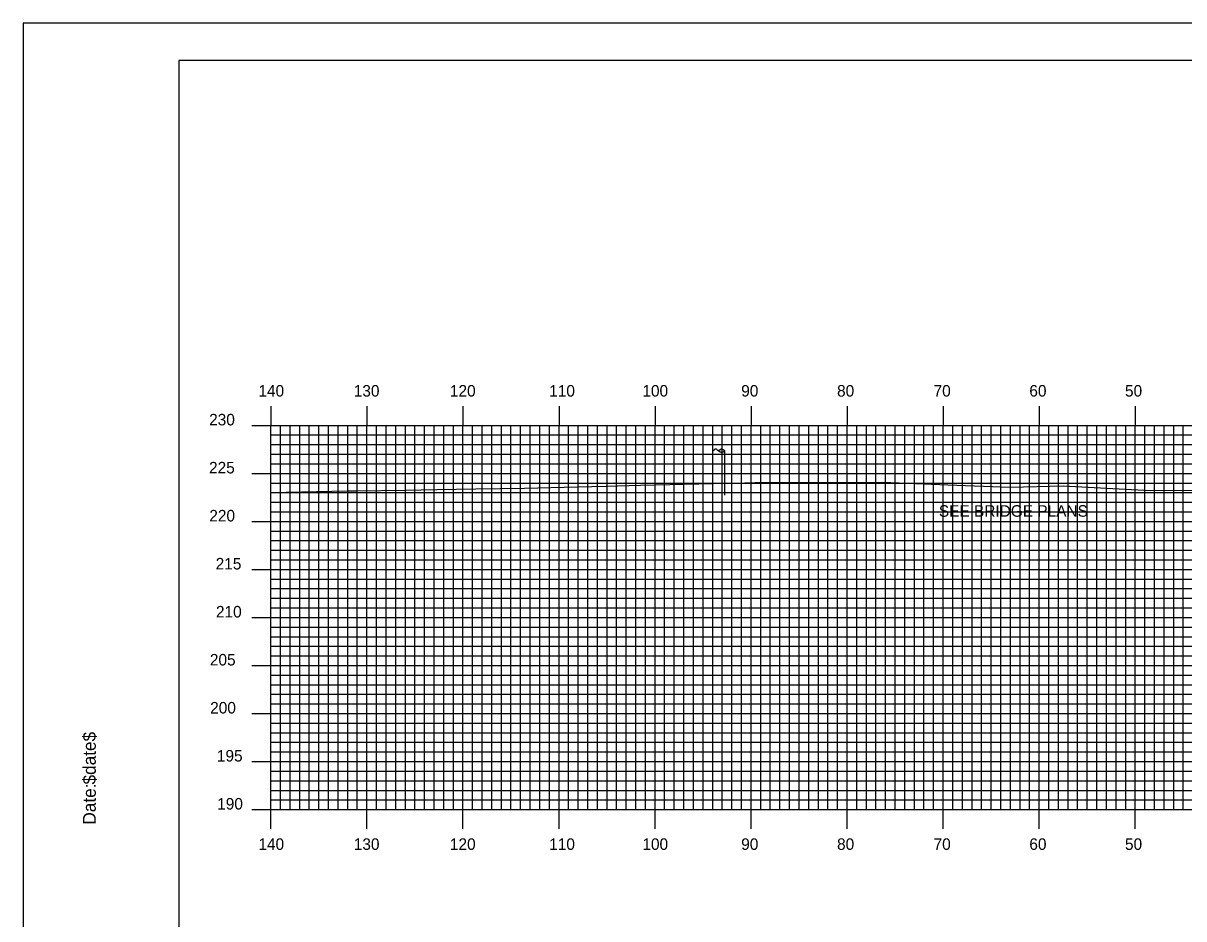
# Model space of a CAD drawing. Extents: x 1800749 to 1801092, y 442591 to 442811.
# Drawn here: x 1800748.8 to 1800869.6, y 442717.3 to 442810.5 of the extents above; entities that cross this region are included whole.
import ezdxf

# ---------------------------------------------------------------- set-up
doc = ezdxf.new("R2010")
doc.units = 0
for name, color, linetype in [('ANNOTATION', 7, 'Continuous'), ('BORDER', 7, 'Continuous'), ('H_V ANNOTATION', 7, 'Continuous'), ('MAJOR', 7, 'Continuous'), ('MINOR', 7, 'Continuous'), ('PLOT BOUNDARY', 7, 'Continuous'), ('S_Roadway_Centerline', 7, 'Continuous'), ('S_Utilities_Pole_Power', 7, 'Continuous')]:
    doc.layers.add(name, color=color, linetype=linetype)

msp = doc.modelspace()

# ---------------------------------------------------------------- linework, layer by layer
at = {"layer": 'BORDER'}
msp.add_lwpolyline([(1800764.95, 442596.67), (1801084.95, 442596.67), (1801084.95, 442806.67), (1800764.95, 442806.67)], close=True, dxfattribs=at)
at = {"layer": 'MAJOR'}
for p, q in [((1800774.55, 442770.67), (1800774.55, 442768.67)), ((1800784.55, 442770.67), (1800784.55, 442768.67)), ((1800794.55, 442770.67), (1800794.55, 442768.67)), ((1800804.55, 442770.67), (1800804.55, 442768.67)), ((1800814.55, 442770.67), (1800814.55, 442768.67)), ((1800824.55, 442770.67), (1800824.55, 442768.67)), ((1800834.55, 442770.67), (1800834.55, 442768.67)), ((1800844.55, 442770.67), (1800844.55, 442768.67)), ((1800854.55, 442770.67), (1800854.55, 442768.67)), ((1800864.55, 442770.67), (1800864.55, 442768.67)), ((1800772.55, 442768.67), (1800774.55, 442768.67)), ((1800774.55, 442768.67), (1801054.55, 442768.67)), ((1800774.55, 442728.67), (1800774.55, 442768.67)), ((1800774.55, 442728.67), (1800774.55, 442768.67)), ((1800774.55, 442768.67), (1801054.55, 442768.67)), ((1800784.55, 442728.67), (1800784.55, 442768.67)), ((1800794.55, 442728.67), (1800794.55, 442768.67)), ((1800804.55, 442728.67), (1800804.55, 442768.67)), ((1800814.55, 442728.67), (1800814.55, 442768.67)), ((1800824.55, 442728.67), (1800824.55, 442768.67)), ((1800834.55, 442728.67), (1800834.55, 442768.67)), ((1800844.55, 442728.67), (1800844.55, 442768.67)), ((1800854.55, 442728.67), (1800854.55, 442768.67)), ((1800864.55, 442728.67), (1800864.55, 442768.67)), ((1800772.55, 442763.67), (1800774.55, 442763.67)), ((1800774.55, 442763.67), (1801054.55, 442763.67)), ((1800772.55, 442758.67), (1800774.55, 442758.67)), ((1800774.55, 442758.67), (1801054.55, 442758.67)), ((1800772.55, 442753.67), (1800774.55, 442753.67)), ((1800774.55, 442753.67), (1801054.55, 442753.67)), ((1800772.55, 442748.67), (1800774.55, 442748.67)), ((1800774.55, 442748.67), (1801054.55, 442748.67)), ((1800772.55, 442743.67), (1800774.55, 442743.67)), ((1800774.55, 442743.67), (1801054.55, 442743.67)), ((1800772.55, 442738.67), (1800774.55, 442738.67)), ((1800774.55, 442738.67), (1801054.55, 442738.67)), ((1800772.55, 442733.67), (1800774.55, 442733.67)), ((1800774.55, 442733.67), (1801054.55, 442733.67)), ((1800772.55, 442728.67), (1800774.55, 442728.67)), ((1800774.55, 442728.67), (1801054.55, 442728.67)), ((1800774.55, 442728.67), (1801054.55, 442728.67)), ((1800774.55, 442726.66), (1800774.55, 442728.67)), ((1800784.55, 442726.66), (1800784.55, 442728.67)), ((1800794.55, 442726.66), (1800794.55, 442728.67)), ((1800804.55, 442726.66), (1800804.55, 442728.67)), ((1800814.55, 442726.66), (1800814.55, 442728.67)), ((1800824.55, 442726.66), (1800824.55, 442728.67)), ((1800834.55, 442726.66), (1800834.55, 442728.67)), ((1800844.55, 442726.66), (1800844.55, 442728.67)), ((1800854.55, 442726.66), (1800854.55, 442728.67)), ((1800864.55, 442726.66), (1800864.55, 442728.67))]:
    msp.add_line(p, q, dxfattribs=at)
at = {"layer": 'MINOR'}
for p, q in [((1800775.55, 442728.67), (1800775.55, 442768.67)), ((1800776.55, 442728.67), (1800776.55, 442768.67)), ((1800777.55, 442728.67), (1800777.55, 442768.67)), ((1800778.55, 442728.67), (1800778.55, 442768.67)), ((1800779.55, 442728.67), (1800779.55, 442768.67)), ((1800780.55, 442728.67), (1800780.55, 442768.67)), ((1800781.55, 442728.67), (1800781.55, 442768.67)), ((1800782.55, 442728.67), (1800782.55, 442768.67)), ((1800783.55, 442728.67), (1800783.55, 442768.67)), ((1800785.55, 442728.67), (1800785.55, 442768.67)), ((1800786.55, 442728.67), (1800786.55, 442768.67)), ((1800787.55, 442728.67), (1800787.55, 442768.67)), ((1800788.55, 442728.67), (1800788.55, 442768.67)), ((1800789.55, 442728.67), (1800789.55, 442768.67)), ((1800790.55, 442728.67), (1800790.55, 442768.67)), ((1800791.55, 442728.67), (1800791.55, 442768.67)), ((1800792.55, 442728.67), (1800792.55, 442768.67)), ((1800793.55, 442728.67), (1800793.55, 442768.67)), ((1800795.55, 442728.67), (1800795.55, 442768.67)), ((1800796.55, 442728.67), (1800796.55, 442768.67)), ((1800797.55, 442728.67), (1800797.55, 442768.67)), ((1800798.55, 442728.67), (1800798.55, 442768.67)), ((1800799.55, 442728.67), (1800799.55, 442768.67)), ((1800800.55, 442728.67), (1800800.55, 442768.67)), ((1800801.55, 442728.67), (1800801.55, 442768.67)), ((1800802.55, 442728.67), (1800802.55, 442768.67)), ((1800803.55, 442728.67), (1800803.55, 442768.67)), ((1800805.55, 442728.67), (1800805.55, 442768.67)), ((1800806.55, 442728.67), (1800806.55, 442768.67)), ((1800807.55, 442728.67), (1800807.55, 442768.67)), ((1800808.55, 442728.67), (1800808.55, 442768.67)), ((1800809.55, 442728.67), (1800809.55, 442768.67)), ((1800810.55, 442728.67), (1800810.55, 442768.67)), ((1800811.55, 442728.67), (1800811.55, 442768.67)), ((1800812.55, 442728.67), (1800812.55, 442768.67)), ((1800813.55, 442728.67), (1800813.55, 442768.67)), ((1800815.55, 442728.67), (1800815.55, 442768.67)), ((1800816.55, 442728.67), (1800816.55, 442768.67)), ((1800817.55, 442728.67), (1800817.55, 442768.67)), ((1800818.55, 442728.67), (1800818.55, 442768.67)), ((1800819.55, 442728.67), (1800819.55, 442768.67)), ((1800820.55, 442728.67), (1800820.55, 442768.67)), ((1800821.55, 442728.67), (1800821.55, 442768.67)), ((1800822.55, 442728.67), (1800822.55, 442768.67)), ((1800823.55, 442728.67), (1800823.55, 442768.67)), ((1800825.55, 442728.67), (1800825.55, 442768.67)), ((1800826.55, 442728.67), (1800826.55, 442768.67)), ((1800827.55, 442728.67), (1800827.55, 442768.67)), ((1800828.55, 442728.67), (1800828.55, 442768.67)), ((1800829.55, 442728.67), (1800829.55, 442768.67)), ((1800830.55, 442728.67), (1800830.55, 442768.67)), ((1800831.55, 442728.67), (1800831.55, 442768.67)), ((1800832.55, 442728.67), (1800832.55, 442768.67)), ((1800833.55, 442728.67), (1800833.55, 442768.67)), ((1800835.55, 442728.67), (1800835.55, 442768.67)), ((1800836.55, 442728.67), (1800836.55, 442768.67)), ((1800837.55, 442728.67), (1800837.55, 442768.67)), ((1800838.55, 442728.67), (1800838.55, 442768.67)), ((1800839.55, 442728.67), (1800839.55, 442768.67)), ((1800840.55, 442728.67), (1800840.55, 442768.67)), ((1800841.55, 442728.67), (1800841.55, 442768.67)), ((1800842.55, 442728.67), (1800842.55, 442768.67)), ((1800843.55, 442728.67), (1800843.55, 442768.67)), ((1800845.55, 442728.67), (1800845.55, 442768.67)), ((1800846.55, 442728.67), (1800846.55, 442768.67)), ((1800847.55, 442728.67), (1800847.55, 442768.67)), ((1800848.55, 442728.67), (1800848.55, 442768.67)), ((1800849.55, 442728.67), (1800849.55, 442768.67)), ((1800850.55, 442728.67), (1800850.55, 442768.67)), ((1800851.55, 442728.67), (1800851.55, 442768.67)), ((1800852.55, 442728.67), (1800852.55, 442768.67)), ((1800853.55, 442728.67), (1800853.55, 442768.67)), ((1800855.55, 442728.67), (1800855.55, 442768.67)), ((1800856.55, 442728.67), (1800856.55, 442768.67)), ((1800857.55, 442728.67), (1800857.55, 442768.67)), ((1800858.55, 442728.67), (1800858.55, 442768.67)), ((1800859.55, 442728.67), (1800859.55, 442768.67)), ((1800860.55, 442728.67), (1800860.55, 442768.67)), ((1800861.55, 442728.67), (1800861.55, 442768.67)), ((1800862.55, 442728.67), (1800862.55, 442768.67)), ((1800863.55, 442728.67), (1800863.55, 442768.67)), ((1800865.55, 442728.67), (1800865.55, 442768.67)), ((1800866.55, 442728.67), (1800866.55, 442768.67)), ((1800867.55, 442728.67), (1800867.55, 442768.67)), ((1800868.55, 442728.67), (1800868.55, 442768.67)), ((1800869.55, 442728.67), (1800869.55, 442768.67)), ((1800774.55, 442767.67), (1801054.55, 442767.67)), ((1800774.55, 442767.67), (1800776.55, 442767.67)), ((1800774.55, 442766.67), (1801054.55, 442766.67)), ((1800774.55, 442766.67), (1800776.55, 442766.67)), ((1800774.55, 442765.67), (1801054.55, 442765.67)), ((1800774.55, 442765.67), (1800776.55, 442765.67)), ((1800774.55, 442764.67), (1801054.55, 442764.67)), ((1800774.55, 442764.67), (1800776.55, 442764.67)), ((1800774.55, 442762.67), (1801054.55, 442762.67)), ((1800774.55, 442762.67), (1800776.55, 442762.67)), ((1800774.55, 442761.67), (1801054.55, 442761.67)), ((1800774.55, 442761.67), (1800776.55, 442761.67)), ((1800774.55, 442760.67), (1801054.55, 442760.67)), ((1800774.55, 442760.67), (1800776.55, 442760.67)), ((1800774.55, 442759.67), (1801054.55, 442759.67)), ((1800774.55, 442759.67), (1800776.55, 442759.67)), ((1800774.55, 442757.67), (1801054.55, 442757.67)), ((1800774.55, 442757.67), (1800776.55, 442757.67)), ((1800774.55, 442756.67), (1801054.55, 442756.67)), ((1800774.55, 442756.67), (1800776.55, 442756.67)), ((1800774.55, 442755.67), (1801054.55, 442755.67)), ((1800774.55, 442755.67), (1800776.55, 442755.67)), ((1800774.55, 442754.67), (1801054.55, 442754.67)), ((1800774.55, 442754.67), (1800776.55, 442754.67)), ((1800774.55, 442752.67), (1801054.55, 442752.67)), ((1800774.55, 442752.67), (1800776.55, 442752.67)), ((1800774.55, 442751.67), (1801054.55, 442751.67)), ((1800774.55, 442751.67), (1800776.55, 442751.67)), ((1800774.55, 442750.67), (1801054.55, 442750.67)), ((1800774.55, 442750.67), (1800776.55, 442750.67)), ((1800774.55, 442749.67), (1801054.55, 442749.67)), ((1800774.55, 442749.67), (1800776.55, 442749.67)), ((1800774.55, 442747.67), (1801054.55, 442747.67)), ((1800774.55, 442747.67), (1800776.55, 442747.67)), ((1800774.55, 442746.67), (1801054.55, 442746.67)), ((1800774.55, 442746.67), (1800776.55, 442746.67)), ((1800774.55, 442745.67), (1801054.55, 442745.67)), ((1800774.55, 442745.67), (1800776.55, 442745.67)), ((1800774.55, 442744.67), (1801054.55, 442744.67)), ((1800774.55, 442744.67), (1800776.55, 442744.67)), ((1800774.55, 442742.67), (1801054.55, 442742.67)), ((1800774.55, 442742.67), (1800776.55, 442742.67)), ((1800774.55, 442741.67), (1801054.55, 442741.67)), ((1800774.55, 442741.67), (1800776.55, 442741.67)), ((1800774.55, 442740.67), (1801054.55, 442740.67)), ((1800774.55, 442740.67), (1800776.55, 442740.67)), ((1800774.55, 442739.67), (1801054.55, 442739.67)), ((1800774.55, 442739.67), (1800776.55, 442739.67)), ((1800774.55, 442737.67), (1801054.55, 442737.67)), ((1800774.55, 442737.67), (1800776.55, 442737.67)), ((1800774.55, 442736.67), (1801054.55, 442736.67)), ((1800774.55, 442736.67), (1800776.55, 442736.67)), ((1800774.55, 442735.67), (1801054.55, 442735.67)), ((1800774.55, 442735.67), (1800776.55, 442735.67)), ((1800774.55, 442734.67), (1801054.55, 442734.67)), ((1800774.55, 442734.67), (1800776.55, 442734.67)), ((1800774.55, 442732.67), (1801054.55, 442732.67)), ((1800774.55, 442732.67), (1800776.55, 442732.67)), ((1800774.55, 442731.67), (1801054.55, 442731.67)), ((1800774.55, 442731.67), (1800776.55, 442731.67)), ((1800774.55, 442730.67), (1801054.55, 442730.67)), ((1800774.55, 442730.67), (1800776.55, 442730.67)), ((1800774.55, 442729.67), (1801054.55, 442729.67)), ((1800774.55, 442729.67), (1800776.55, 442729.67))]:
    msp.add_line(p, q, dxfattribs=at)
at = {"layer": 'PLOT BOUNDARY'}
msp.add_lwpolyline([(1800748.76, 442590.55), (1801088.76, 442590.55), (1801088.76, 442810.55), (1800748.76, 442810.55)], close=True, dxfattribs=at)
at = {"layer": 'S_Roadway_Centerline'}
msp.add_lwpolyline([(1800774.55, 442761.68), (1800782.48, 442761.87), (1800783.53, 442761.86), (1800788.57, 442761.92), (1800791.84, 442761.99), (1800795.88, 442762.05), (1800800.95, 442762.15), (1800806.47, 442762.27), (1800809.47, 442762.34), (1800813.03, 442762.46), (1800820.64, 442762.63), (1800822.81, 442762.67), (1800824.99, 442762.72), (1800830.54, 442762.76), (1800836.47, 442762.71), (1800838.27, 442762.75), (1800845.04, 442762.47), (1800851.52, 442762.23), (1800857.04, 442762.38), (1800866.1, 442761.9), (1800875.81, 442761.91)], dxfattribs=at)
at = {"layer": 'S_Utilities_Pole_Power'}
for p, q in [((1800820.56, 442761.41), (1800820.55, 442766.03)), ((1800820.56, 442766.03), (1800820.71, 442766.14)), ((1800821.02, 442766.14), (1800821.18, 442766.03)), ((1800821.34, 442766.14), (1800821.18, 442766.03)), ((1800821.18, 442766.03), (1800821.34, 442765.92)), ((1800821.81, 442766.03), (1800821.65, 442766.14)), ((1800821.65, 442765.92), (1800821.81, 442766.03)), ((1800821.81, 442761.41), (1800821.8, 442766.03))]:
    msp.add_line(p, q, dxfattribs=at)
for centre, start, end in [((1800820.87, 442765.92), 90, 125.2644), ((1800820.87, 442765.92), 54.7356, 90), ((1800821.49, 442765.92), 90, 125.2644), ((1800821.49, 442766.14), 234.7356, 270), ((1800821.49, 442765.92), 54.7356, 90), ((1800821.49, 442766.14), 270, 305.2644)]:
    msp.add_arc(centre, 0.271, start, end, dxfattribs=at)

# ---------------------------------------------------------------- texts
at = {"layer": 'ANNOTATION'}
msp.add_text('SEE BRIDGE PLANS', height=1.2, dxfattribs=at).set_placement((1800844.1, 442759.16))
at = {"layer": 'BORDER'}
for s, p in [('$date$', (1800756.32, 442731.28)), ('Date:', (1800756.32, 442727.1))]:
    msp.add_text(s, height=1.339, rotation=90, dxfattribs=at).set_placement(p)
at = {"layer": 'H_V ANNOTATION'}
for s, p in [('140', (1800773.25, 442771.67)), ('130', (1800783.18, 442771.67)), ('120', (1800793.19, 442771.67)), ('110', (1800803.53, 442771.67)), ('100', (1800813.23, 442771.67)), ('90', (1800823.52, 442771.67)), ('80', (1800833.5, 442771.67)), ('70', (1800843.55, 442771.67)), ('60', (1800853.52, 442771.67)), ('50', (1800863.48, 442771.67)), ('230', (1800768.12, 442768.67)), ('225', (1800768.11, 442763.67)), ('220', (1800768.14, 442758.67)), ('215', (1800768.8, 442753.67)), ('210', (1800768.83, 442748.67)), ('205', (1800768.2, 442743.67)), ('200', (1800768.23, 442738.67)), ('195', (1800768.93, 442733.67)), ('190', (1800768.96, 442728.67)), ('140', (1800773.25, 442724.47)), ('130', (1800783.18, 442724.47)), ('120', (1800793.19, 442724.47)), ('110', (1800803.53, 442724.47)), ('100', (1800813.23, 442724.47)), ('90', (1800823.52, 442724.47)), ('80', (1800833.5, 442724.47)), ('70', (1800843.55, 442724.47)), ('60', (1800853.52, 442724.47)), ('50', (1800863.48, 442724.47))]:
    msp.add_text(s, height=1.2, dxfattribs=at).set_placement(p)
at = {"layer": 'MAJOR'}
msp.add_text('-', height=0.012, dxfattribs=at).set_placement((1800774.54, 442728.67))
at = {"layer": 'S_Roadway_Centerline'}
for s, p in [('C', (1800782.47, 442761.87)), ('C', (1800782.47, 442761.87)), ('L', (1800782.48, 442761.86)), ('L', (1800782.48, 442761.86))]:
    msp.add_text(s, height=0.0146, dxfattribs=at).set_placement(p)

doc.saveas('drawing.dxf')
